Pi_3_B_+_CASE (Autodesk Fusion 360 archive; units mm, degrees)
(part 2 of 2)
delete_face "DeleteFace6"
delete_face "DeleteFace7"
delete_face "DeleteFace8"
delete_face "DeleteFace9"
extrude "Extrude3" cut of existing geometry blind -1.625
offset_faces "OffsetFaces4" distance 0
delete_face "DeleteFace10"
delete_face "DeleteFace11"
extrude "Extrude4" add of existing geometry blind 10.23
move_face "MoveFace8"
move_face "MoveFace9"
hole "Hole3" HoleDepth 10 HoleDiameter 2
hole "Hole4" HoleDepth 10 HoleDiameter 2
hole "Hole5" HoleDepth 10 HoleDiameter 2
hole "Hole6" HoleDepth 10 HoleDiameter 2
offset_faces "OffsetFaces5" distance 1
move_face "MoveFace6"
delete_face "DeleteFace23"
offset_faces "OffsetFaces23" distance 0.4
offset_faces "OffsetFaces24" distance 0.4
delete_face "DeleteFace24"
extrude "Extrude14" cut sketch "Sketch16" along normal blind 8
sketch "Sketch17" plane through (0, 0, 36.4) normal (0, 0, -1) x axis (1, 0, 0)
  line L1 (-29.8898, 23.7088) -> (10.2102, 23.7088)
  line L2 (-29.8898, -16.3912) -> (-29.8898, 23.7088)
  line L3 (10.2102, -16.3912) -> (-29.8898, -16.3912)
  line L4 (10.2102, 23.7088) -> (10.2102, -16.3912)
  curve K1 (5.814, -7.1095) -> (6.1601, -6.5881)
  curve K2 (6.5567, -5.9409) -> (6.8647, -5.3942)
  circle C1 centre (6.1602, -12.3412) radius 1.725
  circle C2 centre (-25.8398, -12.3412) radius 1.725
  circle C3 centre (-25.8398, 19.6588) radius 1.725
  circle C4 centre (6.1602, 19.6588) radius 1.725
  arc A1 centre (-9.8398, 3.6588) radius 19 clockwise from (-27.0735, -4.3412) to (-10.5162, 22.6468)
  arc A2 centre (-9.8398, 3.6588) radius 19 clockwise from (-25.9457, -6.4209) to (-27.0735, -4.3412)
  arc A3 centre (-9.8398, 3.6588) radius 19 clockwise from (4.5049, -8.8003) to (-25.9457, -6.4209)
  arc A4 centre (-9.8398, 3.6588) radius 19 clockwise from (5.814, -7.1095) to (4.5049, -8.8003)
  arc A5 centre (-9.8398, 3.6588) radius 19 clockwise from (6.5567, -5.9409) to (6.1601, -6.5881)
  arc A6 centre (-9.8398, 3.6588) radius 19 clockwise from (8.2681, -2.0948) to (6.8647, -5.3942)
  arc A7 centre (-9.8398, 3.6588) radius 19 clockwise from (-8.1512, 22.5836) to (8.2681, -2.0948)
  arc A8 centre (-9.8398, 3.6588) radius 19 clockwise from (-10.5162, 22.6468) to (-8.1512, 22.5836)
  circle C5 centre (-9.8398, 3.6588) radius 19
hole "Hole3" HoleDepth 10 HoleDiameter 3.3
extrude "Extrude16" cut sketch "Sketch17" profile of A1 A2 A3 A4 K1 A5 K2 A6 A7 A8 C5 against normal blind 2
move_face "MoveFace7"
delete_face "DeleteFace25"
move_face "MoveFace8"
delete_face "DeleteFace26"
chamfer "Chamfer17" distance 0.5
chamfer "Chamfer18" distance 0.3
delete_face "DeleteFace27"
chamfer "Chamfer19" distance 0.3
delete_face "DeleteFace19"
delete_face "DeleteFace20"
delete_face "DeleteFace21"
offset_faces "OffsetFaces10" distance 2
delete_face "DeleteFace22"
chamfer "Chamfer11" distance 3
chamfer "Chamfer12" distance 0.2
fillet "Fillet1" radius 0.5
offset_faces "OffsetFaces11" distance 0.8
offset_faces "OffsetFaces25" distance -0.8
sketch "Sketch18" plane through (0, -24.4, 0) normal (0, 1, 0) x axis (-1, 0, 0)
  line L1 (-18.7605, 30.4) -> (-18.7605, 28.5)
  line L2 (-23.0398, 30.4) -> (-18.7605, 30.4)
  line L3 (-23.0398, 30.3) -> (-23.0398, 30.4)
  line L4 (-43.0097, 30.3) -> (-23.0398, 30.3)
  line L5 (-43.0097, 32.5) -> (-43.0097, 30.3)
  line L6 (-26.9398, 32.5) -> (-43.0097, 32.5)
  line L7 (-26.9398, 35.9) -> (-26.9398, 32.5)
  line L8 (-23.4043, 38.4) -> (-26.9398, 35.9)
  line L9 (-39.9031, 38.4) -> (-23.4043, 38.4)
  line L10 (-52.1398, 26.1633) -> (-39.9031, 38.4)
  line L11 (-52.1398, 25.701) -> (-52.1398, 26.1633)
  line L12 (-51.3898, 25.1706) -> (-52.1398, 25.701)
  line L13 (-51.3898, 16.7) -> (-51.3898, 25.1706)
  line L14 (-47.1398, 16.7) -> (-51.3898, 16.7)
  line L15 (-47.1398, 26.9206) -> (-47.1398, 16.7)
  line L16 (-45.5605, 28.5) -> (-47.1398, 26.9206)
  line L17 (-18.7605, 28.5) -> (-45.5605, 28.5)
  line L18 (-22.4398, 38.4) -> (-24.9398, 35.9)
  line L19 (-24.9398, 35.9) -> (-22.4398, 38.4)
  line L20 (-27.0398, 35.4) -> (-42.9031, 35.4)
  line L21 (-24.9398, 32.5) -> (-24.9398, 35.9)
  line L22 (-24.9398, 35.9) -> (-24.9398, 32.5)
  line L23 (32.8171, 35.4) -> (36.3171, 35.4)
  line L24 (-12.8219, 35.4) -> (32.8171, 35.4)
  line L25 (-16.3219, 35.4) -> (-12.8219, 35.4)
  line L26 (-22.9984, 35.4) -> (-16.3219, 35.4)
  line L27 (-25.0398, 35.4) -> (-22.9984, 35.4)
  line L28 (-27.0398, 35.4) -> (-25.0398, 35.4)
  line L29 (-42.9031, 35.4) -> (-27.0398, 35.4)
  line L30 (-35.5602, 35.4) -> (-42.9031, 35.4)
  line L31 (-35.5602, 35.4) -> (-30.1602, 35.4)
  line L32 (24.4398, 35.4) -> (-30.1602, 35.4)
  line L33 (24.4398, 35.4) -> (29.8398, 35.4)
  line L34 (39.5992, 35.4) -> (29.8398, 35.4)
  line L35 (36.4992, 35.4) -> (39.5992, 35.4)
  line L36 (36.3171, 35.4) -> (36.4992, 35.4)
  line L37 (-39.9031, 38.4) -> (-52.1398, 26.1633)
  line L38 (-23.4043, 38.4) -> (-39.9031, 38.4)
  line L39 (-23.4043, 38.4) -> (-22.4398, 38.4)
  line L40 (-26.9398, 35.9) -> (-23.4043, 38.4)
  line L41 (-24.9398, 35.9) -> (-26.9398, 35.9)
  line L42 (-22.4398, 38.4) -> (-24.9398, 35.9)
extrude "Extrude17" add sketch "Sketch18" profile of L7 L8 L9 L10 L18 L19 L20 L21 L22 L27 L28 L29 L30 L31 L32 L37 L38 L39 L40 L41 L42 along normal blind 10
chamfer "Chamfer20" distance 2.5
work_plane "WorkPlane14"
work_plane "WorkPlane15" AlongDistance 0.5
split "Split4"
split "Split5" bodies "TOP (1) (2)"
combine "Combine4"
remove_body "RemoveBody1"
chamfer "Chamfer21" distance 2.5
chamfer "Chamfer22" distance 2
sketch "Sketch20" plane through (0, 0, 38.4) normal (0, 0, 1) x axis (-1, 0, 0)
  line L1 (-37.4536, 16.9) -> (-39.9031, 19.3495)
  line L2 (-22.4398, 16.9) -> (-37.4536, 16.9)
  line L3 (-22.4398, -17.8816) -> (-22.4398, 16.9)
  line L4 (-20.4215, -19.9) -> (-22.4398, -17.8816)
  line L5 (36.9548, -19.9) -> (-20.4215, -19.9)
  line L6 (40.6992, -23.6444) -> (36.9548, -19.9)
  line L7 (40.6992, -34) -> (40.6992, -23.6444)
  line L8 (43.8173, -34) -> (40.6992, -34)
  line L9 (43.8173, 32) -> (43.8173, -34)
  line L10 (34.5978, 32) -> (43.8173, 32)
  line L11 (34.5978, 31) -> (34.5978, 32)
  line L12 (28.9978, 32) -> (28.9978, 31)
  line L13 (-25.0412, 32) -> (28.9978, 32)
  line L14 (-25.0412, 31) -> (-25.0412, 32)
  line L15 (-30.6412, 32) -> (-30.6412, 31)
  line L16 (-39.9031, 32) -> (-30.6412, 32)
  line L17 (-39.9031, 19.3495) -> (-39.9031, 32)
  line L18 (32.9031, 25.5) -> (32.9031, -8.5)
  line L19 (36.9031, -8.5) -> (36.9031, 25.5)
  line L20 (-15.0969, 25.5) -> (-15.0969, -13.5)
  line L21 (-11.0969, -13.5) -> (-11.0969, 25.5)
  line L22 (34.9031, 20.5) -> (34.9031, 25.5)
  line L23 (33.4031, 25.5) -> (33.4031, -8.5)
  line L24 (36.4031, -8.5) -> (36.4031, 25.5)
  line L25 (29.9898, -20.7569) -> (29.9898, 20.9998)
  line L26 (35.0541, -20.7569) -> (29.9898, -20.7569)
  line L27 (36.6398, -22.3427) -> (35.0541, -20.7569)
  line L28 (36.6398, -26.6671) -> (36.6398, -22.3427)
  line L29 (39.7185, -11.482) -> (39.7185, -26.6201)
  line L30 (38.3561, -11.482) -> (39.7185, -11.482)
  line L31 (37.2703, -10.3962) -> (38.3561, -11.482)
  line L32 (37.2703, 11.8322) -> (37.2703, -10.3962)
  line L33 (38.3561, 12.918) -> (37.2703, 11.8322)
  line L34 (39.7185, 12.918) -> (38.3561, 12.918)
  line L35 (39.7185, 29) -> (39.7185, 12.918)
  line L36 (42.125, 29) -> (39.7185, 29)
  line L37 (42.8321, 29.5) -> (42.125, 29)
  line L38 (42.8321, 35) -> (42.8321, 29.5)
  line L39 (-41.3524, 35) -> (42.8321, 35)
  line L40 (-41.3524, 29.5) -> (-41.3524, 35)
  line L41 (-20.0388, 29.5) -> (-41.3524, 29.5)
  line L42 (-20.0388, -26.6201) -> (-20.0388, 29.5)
  line L43 (-16.9602, -22.3427) -> (-16.9602, -26.6671)
  line L44 (-15.3744, -20.7569) -> (-16.9602, -22.3427)
  line L45 (-10.3102, -20.7569) -> (-15.3744, -20.7569)
  line L46 (-10.3102, 20.9998) -> (-10.3102, -20.7569)
  line L47 (25.9898, 24.9998) -> (-6.3102, 24.9998)
  line L48 (-11.323, -13.3412) -> (-11.3102, -13.3412)
  line L49 (-12.7664, -10.8412) -> (-11.323, -13.3412)
  line L50 (-11.323, -8.3412) -> (-12.7664, -10.8412)
  line L51 (-11.3102, -8.3412) -> (-11.323, -8.3412)
  line L52 (-11.3102, -13.3412) -> (-11.3102, -8.3412)
  line L53 (-11.3102, 15.6588) -> (-11.3102, 20.6588)
  line L54 (-11.323, 15.6588) -> (-11.3102, 15.6588)
  line L55 (-12.7664, 18.1588) -> (-11.323, 15.6588)
  line L56 (-11.323, 20.6588) -> (-12.7664, 18.1588)
  line L57 (-11.3102, 20.6588) -> (-11.323, 20.6588)
  line L58 (-11.3102, 9.8588) -> (-11.3102, 14.8588)
  line L59 (-11.323, 9.8588) -> (-11.3102, 9.8588)
  line L60 (-12.7664, 12.3588) -> (-11.323, 9.8588)
  line L61 (-11.323, 14.8588) -> (-12.7664, 12.3588)
  line L62 (-11.3102, 14.8588) -> (-11.323, 14.8588)
  line L63 (-11.3102, 4.0588) -> (-11.3102, 9.0588)
  line L64 (-11.323, 4.0588) -> (-11.3102, 4.0588)
  line L65 (-12.7664, 6.5588) -> (-11.323, 4.0588)
  line L66 (-11.323, 9.0588) -> (-12.7664, 6.5588)
  line L67 (-11.3102, 9.0588) -> (-11.323, 9.0588)
  line L68 (-11.3102, -1.7412) -> (-11.3102, 3.2588)
  line L69 (-11.323, -1.7412) -> (-11.3102, -1.7412)
  line L70 (-12.7664, 0.7588) -> (-11.323, -1.7412)
  line L71 (-11.323, 3.2588) -> (-12.7664, 0.7588)
  line L72 (-11.3102, 3.2588) -> (-11.323, 3.2588)
  line L73 (-15.1602, 1.1588) -> (-13.4592, 1.1588)
  line L74 (-15.1602, 6.1588) -> (-15.1602, 1.1588)
  line L75 (-13.4592, 6.1588) -> (-15.1602, 6.1588)
  line L76 (-12.0158, 3.6588) -> (-13.4592, 6.1588)
  line L77 (-13.4592, 1.1588) -> (-12.0158, 3.6588)
  line L78 (-15.1602, -5.4412) -> (-15.1602, -10.4412)
  line L79 (-13.4592, -5.4412) -> (-15.1602, -5.4412)
  line L80 (-12.0158, -7.9412) -> (-13.4592, -5.4412)
  line L81 (-13.4592, -10.4412) -> (-12.0158, -7.9412)
  line L82 (-15.1602, -10.4412) -> (-13.4592, -10.4412)
  line L83 (-15.1602, 0.3588) -> (-15.1602, -4.6412)
  line L84 (-13.4592, 0.3588) -> (-15.1602, 0.3588)
  line L85 (-12.0158, -2.1412) -> (-13.4592, 0.3588)
  line L86 (-13.4592, -4.6412) -> (-12.0158, -2.1412)
  line L87 (-15.1602, -4.6412) -> (-13.4592, -4.6412)
  line L88 (-13.4592, 11.9588) -> (-15.1602, 11.9588)
  line L89 (-12.0158, 9.4588) -> (-13.4592, 11.9588)
  line L90 (-13.4592, 6.9588) -> (-12.0158, 9.4588)
  line L91 (-15.1602, 6.9588) -> (-13.4592, 6.9588)
  line L92 (-15.1602, 11.9588) -> (-15.1602, 6.9588)
  line L93 (-15.1602, 17.7588) -> (-15.1602, 12.7588)
  line L94 (-13.4592, 17.7588) -> (-15.1602, 17.7588)
  line L95 (-12.0158, 15.2588) -> (-13.4592, 17.7588)
  line L96 (-13.4592, 12.7588) -> (-12.0158, 15.2588)
  line L97 (-15.1602, 12.7588) -> (-13.4592, 12.7588)
  line L98 (-11.3102, -7.5412) -> (-11.3102, -2.5412)
  line L99 (-11.323, -7.5412) -> (-11.3102, -7.5412)
  line L100 (-12.7664, -5.0412) -> (-11.323, -7.5412)
  line L101 (-11.323, -2.5412) -> (-12.7664, -5.0412)
  line L102 (-11.3102, -2.5412) -> (-11.323, -2.5412)
  line L103 (30.9898, -8.3412) -> (30.9898, -13.3412)
  line L104 (31.7473, -8.3412) -> (30.9898, -8.3412)
  line L105 (33.1907, -10.8412) -> (31.7473, -8.3412)
  line L106 (31.7473, -13.3412) -> (33.1907, -10.8412)
  line L107 (30.9898, -13.3412) -> (31.7473, -13.3412)
  line L108 (31.7473, 14.8588) -> (30.9898, 14.8588)
  line L109 (33.1907, 12.3588) -> (31.7473, 14.8588)
  line L110 (31.7473, 9.8588) -> (33.1907, 12.3588)
  line L111 (30.9898, 9.8588) -> (31.7473, 9.8588)
  line L112 (30.9898, 14.8588) -> (30.9898, 9.8588)
  line L113 (31.7473, 9.0588) -> (30.9898, 9.0588)
  line L114 (33.1907, 6.5588) -> (31.7473, 9.0588)
  line L115 (31.7473, 4.0588) -> (33.1907, 6.5588)
  line L116 (30.9898, 4.0588) -> (31.7473, 4.0588)
  line L117 (30.9898, 9.0588) -> (30.9898, 4.0588)
  line L118 (31.7473, 3.2588) -> (30.9898, 3.2588)
  line L119 (33.1907, 0.7588) -> (31.7473, 3.2588)
  line L120 (31.7473, -1.7412) -> (33.1907, 0.7588)
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  point P28 (34.9031, 25.5)
  point P41 (34.9031, 25.5)
  point P42 (34.9031, 20.5)
  point P43 (34.9031, 20.5)
  coincident P28 P41
  vertical L22
  coincident P42 P43
  dimension "d238" distance P41 P42 = 5
extrude "Extrude19" add sketch "Sketch20" against normal blind 8
chamfer "Chamfer24" distance 0.5
offset_faces "OffsetFaces26" distance -3.536
delete_face "DeleteFace28"
chamfer "Chamfer25" distance 3
remove_instance "RemoveInstance1"
offset_faces "OffsetFaces6" distance 1
work_axis "WorkAxis5"
work_plane "WorkPlane16"
work_plane "WorkPlane17" AlongDistance -50
move_face "MoveFace9"
position "Position18"
position "Position19"
move_face "MoveFace10"
sketch "Sketch21" plane through (0, 0, 28.4) normal (0, 0, 1) x axis (-1, 0, 0)
  line L1 (29.9898, -20.7569) -> (29.9898, 20.9998)
  line L2 (35.0541, -20.7569) -> (29.9898, -20.7569)
  line L3 (36.6398, -22.3427) -> (35.0541, -20.7569)
  line L4 (36.6398, -26.6671) -> (36.6398, -22.3427)
  line L5 (39.7185, -11.482) -> (39.7185, -26.6201)
  line L6 (38.3561, -11.482) -> (39.7185, -11.482)
  line L7 (37.2703, -10.3962) -> (38.3561, -11.482)
  line L8 (37.2703, 11.8322) -> (37.2703, -10.3962)
  line L9 (38.3561, 12.918) -> (37.2703, 11.8322)
  line L10 (39.7185, 12.918) -> (38.3561, 12.918)
  line L11 (39.7185, 29) -> (39.7185, 12.918)
  line L12 (42.125, 29) -> (39.7185, 29)
  line L13 (42.8321, 29.5) -> (42.125, 29)
  line L14 (42.8321, 35) -> (42.8321, 29.5)
  line L15 (-41.3524, 35) -> (42.8321, 35)
  line L16 (-41.3524, 29.5) -> (-41.3524, 35)
  line L17 (-20.0388, 29.5) -> (-41.3524, 29.5)
  line L18 (-20.0388, -26.6201) -> (-20.0388, 29.5)
  line L19 (-16.9602, -22.3427) -> (-16.9602, -26.6671)
  line L20 (-15.3744, -20.7569) -> (-16.9602, -22.3427)
  line L21 (-10.3102, -20.7569) -> (-15.3744, -20.7569)
  line L22 (-10.3102, 20.9998) -> (-10.3102, -20.7569)
  line L23 (25.9898, 24.9998) -> (-6.3102, 24.9998)
  line L24 (-11.323, -13.3412) -> (-11.3102, -13.3412)
  line L25 (-12.7664, -10.8412) -> (-11.323, -13.3412)
  line L26 (-11.323, -8.3412) -> (-12.7664, -10.8412)
  line L27 (-11.3102, -8.3412) -> (-11.323, -8.3412)
  line L28 (-11.3102, -13.3412) -> (-11.3102, -8.3412)
  line L29 (-11.3102, 15.6588) -> (-11.3102, 20.6588)
  line L30 (-11.323, 15.6588) -> (-11.3102, 15.6588)
  line L31 (-12.7664, 18.1588) -> (-11.323, 15.6588)
  line L32 (-11.323, 20.6588) -> (-12.7664, 18.1588)
  line L33 (-11.3102, 20.6588) -> (-11.323, 20.6588)
  line L34 (-11.3102, 9.8588) -> (-11.3102, 14.8588)
  line L35 (-11.323, 9.8588) -> (-11.3102, 9.8588)
  line L36 (-12.7664, 12.3588) -> (-11.323, 9.8588)
  line L37 (-11.323, 14.8588) -> (-12.7664, 12.3588)
  line L38 (-11.3102, 14.8588) -> (-11.323, 14.8588)
  line L39 (-11.3102, 4.0588) -> (-11.3102, 9.0588)
  line L40 (-11.323, 4.0588) -> (-11.3102, 4.0588)
  line L41 (-12.7664, 6.5588) -> (-11.323, 4.0588)
  line L42 (-11.323, 9.0588) -> (-12.7664, 6.5588)
  line L43 (-11.3102, 9.0588) -> (-11.323, 9.0588)
  line L44 (-11.3102, -1.7412) -> (-11.3102, 3.2588)
  line L45 (-11.323, -1.7412) -> (-11.3102, -1.7412)
  line L46 (-12.7664, 0.7588) -> (-11.323, -1.7412)
  line L47 (-11.323, 3.2588) -> (-12.7664, 0.7588)
  line L48 (-11.3102, 3.2588) -> (-11.323, 3.2588)
  line L49 (-15.1602, 1.1588) -> (-13.4592, 1.1588)
  line L50 (-15.1602, 6.1588) -> (-15.1602, 1.1588)
  line L51 (-13.4592, 6.1588) -> (-15.1602, 6.1588)
  line L52 (-12.0158, 3.6588) -> (-13.4592, 6.1588)
  line L53 (-13.4592, 1.1588) -> (-12.0158, 3.6588)
  line L54 (-15.1602, -5.4412) -> (-15.1602, -10.4412)
  line L55 (-13.4592, -5.4412) -> (-15.1602, -5.4412)
  line L56 (-12.0158, -7.9412) -> (-13.4592, -5.4412)
  line L57 (-13.4592, -10.4412) -> (-12.0158, -7.9412)
  line L58 (-15.1602, -10.4412) -> (-13.4592, -10.4412)
  line L59 (-15.1602, 0.3588) -> (-15.1602, -4.6412)
  line L60 (-13.4592, 0.3588) -> (-15.1602, 0.3588)
  line L61 (-12.0158, -2.1412) -> (-13.4592, 0.3588)
  line L62 (-13.4592, -4.6412) -> (-12.0158, -2.1412)
  line L63 (-15.1602, -4.6412) -> (-13.4592, -4.6412)
  line L64 (-13.4592, 11.9588) -> (-15.1602, 11.9588)
  line L65 (-12.0158, 9.4588) -> (-13.4592, 11.9588)
  line L66 (-13.4592, 6.9588) -> (-12.0158, 9.4588)
  line L67 (-15.1602, 6.9588) -> (-13.4592, 6.9588)
  line L68 (-15.1602, 11.9588) -> (-15.1602, 6.9588)
  line L69 (-15.1602, 17.7588) -> (-15.1602, 12.7588)
  line L70 (-13.4592, 17.7588) -> (-15.1602, 17.7588)
  line L71 (-12.0158, 15.2588) -> (-13.4592, 17.7588)
  line L72 (-13.4592, 12.7588) -> (-12.0158, 15.2588)
  line L73 (-15.1602, 12.7588) -> (-13.4592, 12.7588)
  line L74 (-11.3102, -7.5412) -> (-11.3102, -2.5412)
  line L75 (-11.323, -7.5412) -> (-11.3102, -7.5412)
  line L76 (-12.7664, -5.0412) -> (-11.323, -7.5412)
  line L77 (-11.323, -2.5412) -> (-12.7664, -5.0412)
  line L78 (-11.3102, -2.5412) -> (-11.323, -2.5412)
  line L79 (30.9898, -8.3412) -> (30.9898, -13.3412)
  line L80 (31.7473, -8.3412) -> (30.9898, -8.3412)
  line L81 (33.1907, -10.8412) -> (31.7473, -8.3412)
  line L82 (31.7473, -13.3412) -> (33.1907, -10.8412)
  line L83 (30.9898, -13.3412) -> (31.7473, -13.3412)
  line L84 (31.7473, 14.8588) -> (30.9898, 14.8588)
  line L85 (33.1907, 12.3588) -> (31.7473, 14.8588)
  line L86 (31.7473, 9.8588) -> (33.1907, 12.3588)
  line L87 (30.9898, 9.8588) -> (31.7473, 9.8588)
  line L88 (30.9898, 14.8588) -> (30.9898, 9.8588)
  line L89 (31.7473, 9.0588) -> (30.9898, 9.0588)
  line L90 (33.1907, 6.5588) -> (31.7473, 9.0588)
  line L91 (31.7473, 4.0588) -> (33.1907, 6.5588)
  line L92 (30.9898, 4.0588) -> (31.7473, 4.0588)
  line L93 (30.9898, 9.0588) -> (30.9898, 4.0588)
  line L94 (31.7473, 3.2588) -> (30.9898, 3.2588)
  line L95 (33.1907, 0.7588) -> (31.7473, 3.2588)
  line L96 (31.7473, -1.7412) -> (33.1907, 0.7588)
  line L97 (30.9898, -1.7412) -> (31.7473, -1.7412)
  line L98 (30.9898, 3.2588) -> (30.9898, -1.7412)
  line L99 (31.7473, -2.5412) -> (30.9898, -2.5412)
  line L100 (33.1907, -5.0412) -> (31.7473, -2.5412)
  line L101 (31.7473, -7.5412) -> (33.1907, -5.0412)
  line L102 (30.9898, -7.5412) -> (31.7473, -7.5412)
  line L103 (30.9898, -2.5412) -> (30.9898, -7.5412)
  line L104 (30.9898, 20.6588) -> (30.9898, 15.6588)
  line L105 (31.7473, 20.6588) -> (30.9898, 20.6588)
  line L106 (33.1907, 18.1588) -> (31.7473, 20.6588)
  line L107 (31.7473, 15.6588) -> (33.1907, 18.1588)
  line L108 (30.9898, 15.6588) -> (31.7473, 15.6588)
  line L109 (34.8398, 6.1588) -> (33.8835, 6.1588)
  line L110 (34.8398, 1.1588) -> (34.8398, 6.1588)
  line L111 (33.8835, 1.1588) -> (34.8398, 1.1588)
  line L112 (32.4402, 3.6588) -> (33.8835, 1.1588)
  line L113 (33.8835, 6.1588) -> (32.4402, 3.6588)
  line L114 (34.8398, -4.6412) -> (34.8398, 0.3588)
  line L115 (33.8835, -4.6412) -> (34.8398, -4.6412)
  line L116 (32.4402, -2.1412) -> (33.8835, -4.6412)
  line L117 (33.8835, 0.3588) -> (32.4402, -2.1412)
  line L118 (34.8398, 0.3588) -> (33.8835, 0.3588)
  line L119 (34.8398, 11.9588) -> (33.8835, 11.9588)
  line L120 (34.8398, 6.9588) -> (34.8398, 11.9588)
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hole "Hole1" HoleDepth 6.4 HoleDiameter 2
component_insert "Component Insert"
step "00000000-0000-0000-0000-000000000000"
base_feature "Base Feature1"
position "Position20"
step "00000000-0000-0000-0000-000000000000"
offset_faces "OffsetFaces1" distance 5
work_plane "WorkPlane18" AlongDistance 0
sketch "Sketch22" plane through (-1.9571, -1.5003, 38.4) normal (0, 0, 1) x axis (1, 0, 0)
  line L1 (-43.1827, -12.5382) -> (-43.1827, 15.0673)
  line L2 (-37.946, 10.0003) -> (-32.946, 10.0003)
  line L3 (-46.446, 11.5003) -> (-39.446, 11.5003)
  line L4 (-39.446, 8.5003) -> (-46.446, 8.5003)
  line L5 (-47.946, 10.0003) -> (-37.946, 10.0003)
  arc A1 centre (-32.946, 10.0003) radius 1.5 clockwise from (-34.446, 10.0003) to (-31.446, 10.0003)
  arc A2 centre (-46.446, 10.0003) radius 1.5 clockwise from (-46.446, 8.5003) to (-46.446, 11.5003)
  arc A3 centre (-39.446, 10.0003) radius 1.5 clockwise from (-39.446, 11.5003) to (-39.446, 8.5003)
  point P4 (-32.946, 10.0003)
  point P7 (-32.946, 10.0003)
  point P8 (-37.946, 10.0003)
  point P15 (-47.946, 10.0003)
  coincident P4 P7
  perpendicular L1 L2
  tangent L3 A2
  tangent A2 L4
  parallel L3 L4
  tangent L4 A3
  tangent L3 A3
  midpoint P8 A3
  midpoint A2 P15
  perpendicular L1 L5
  dimension "d259" distance P7 P8 = 5
  dimension "d260" diameter A2 = 3
emboss "Emboss1" sketch "Sketch22" Depth -10.895 Horizontal Distance -4.25 Vertical Distance 2
rectangular_pattern "R-Pattern2" uSpaceDistance -35 vSpaceDistance 0
chamfer "Chamfer26" distance 0.3
sketch "Sketch23" plane through (0, 0, 35.4) normal (0, 0, 1) x axis (-1, 0, 0)
  line L1 (36.3171, -25.269) -> (36.3171, -21)
  line L2 (-12.8219, -28.769) -> (32.8171, -28.769)
  line L3 (-16.3219, -21) -> (-16.3219, -25.269)
  line L4 (-22.9984, -21) -> (-16.3219, -21)
  line L5 (-25.0398, -18.9586) -> (-22.9984, -21)
  line L6 (-25.0398, 22.3) -> (-25.0398, -18.9586)
  line L7 (-27.0398, 24.3) -> (-25.0398, 22.3)
  line L8 (-42.9031, 24.3) -> (-27.0398, 24.3)
  line L9 (-42.9031, -32) -> (-42.9031, 24.3)
  line L10 (-35.5602, -32) -> (-42.9031, -32)
  line L11 (24.4398, -32) -> (-30.1602, -32)
  line L12 (39.5992, -32) -> (29.8398, -32)
  line L13 (39.5992, -24.1) -> (39.5992, -32)
  line L14 (36.4992, -21) -> (39.5992, -24.1)
  line L15 (36.3171, -21) -> (36.4992, -21)
  line L16 (-27.0398, 11.4) -> (-25.0398, 11.4)
  line L17 (-24.9398, 14.4) -> (-39.9031, 14.4)
  line L18 (-23.0398, 11.4) -> (-27.0398, 11.4)
  line L19 (-27.0398, 11.4) -> (-25.0398, 11.4)
  line L20 (-39.7678, 0.7934) -> (-29.1612, 11.4)
  line L21 (-27.0398, 9.2787) -> (-37.6464, -1.3279)
  line L22 (-39.7678, -1.3279) -> (-27.0398, 11.4)
  line L23 (-12.0398, 11.4) -> (-27.0398, 11.4)
  line L24 (-37.6464, 11.4) -> (-27.0398, 0.7934)
  line L25 (-29.1612, -1.3279) -> (-39.7678, 9.2787)
  line L26 (-33.5398, 12.9) -> (-28.5398, 12.9)
  line L27 (-28.5398, 9.9) -> (-33.5398, 9.9)
  line L28 (-35.0398, 11.4) -> (-27.0398, 11.4)
  arc A1 centre (32.8171, -25.269) radius 3.5 clockwise from (36.3171, -25.269) to (32.8171, -28.769)
  arc A2 centre (-12.8219, -25.269) radius 3.5 clockwise from (-12.8219, -28.769) to (-16.3219, -25.269)
  arc A3 centre (-32.8602, -32) radius 2.7 clockwise from (-35.5602, -32) to (-30.1602, -32)
  arc A4 centre (27.1398, -32) radius 2.7 clockwise from (24.4398, -32) to (29.8398, -32)
  arc A5 centre (-38.7071, -0.2673) radius 1.5 clockwise from (-37.6464, -1.3279) to (-39.7678, 0.7934)
  arc A6 centre (-28.1005, 10.3393) radius 1.5 clockwise from (-29.1612, 11.4) to (-27.0398, 9.2787)
  arc A7 centre (-38.7071, 10.3393) radius 1.5 clockwise from (-39.7678, 9.2787) to (-37.6464, 11.4)
  arc A8 centre (-28.1005, -0.2673) radius 1.5 clockwise from (-27.0398, 0.7934) to (-29.1612, -1.3279)
  arc A9 centre (-33.5398, 11.4) radius 1.5 clockwise from (-33.5398, 9.9) to (-33.5398, 12.9)
  arc A10 centre (-28.5398, 11.4) radius 1.5 clockwise from (-28.5398, 12.9) to (-28.5398, 9.9)
  point P25 (-25.0398, 11.4)
  point P26 (-27.0398, 11.4)
  point P37 (-39.7678, -1.3279)
  point P39 (-33.4038, 5.036)
  point P52 (-35.0398, 11.4)
  point P30 (-27.0398, 11.4)
  coincident L6 P25
  perpendicular L6 L16
  parallel L16 L18
  perpendicular L6 L19
  tangent L20 A5
  tangent A5 L21
  parallel L20 L21
  tangent L21 A6
  tangent L20 A6
  midpoint P26 A6
  midpoint A5 P37
  midpoint L22 P39
  tangent L24 A7
  tangent A7 L25
  parallel L24 L25
  tangent L25 A8
  tangent L24 A8
  tangent L26 A9
  tangent A9 L27
  parallel L26 L27
  tangent L27 A10
  tangent L26 A10
  midpoint P26 A10
  midpoint A9 P52
  parallel L18 L28
  dimension "d271" distance L16 L17 = 3
  dimension "d283" distance P25 P30 = 2
  dimension "d284" distance P26 P37 = 18
  dimension "d285" angle L22 L23 = 135 (= "Angular Dimension-2")
  dimension "d286" diameter A5 = 3
  dimension "d295" diameter A7 = 3
  dimension "d296" diameter A9 = 3
extrude "Extrude7" cut sketch "Sketch23" profile of L20 A6 L26 A9 L27 A10 against normal blind 5
chamfer "Chamfer14" distance 0.3
rectangular_pattern "R-Pattern3" uSpaceDistance 35 vSpaceDistance 0
chamfer "Chamfer15" distance 0.3
delete_face "DeleteFace23"
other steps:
base_feature "Base Feature1" bodies "PI3 A/B_MOUNT  (1) (2)"
move_face "MoveFace3"
offset_faces "OffsetFaces2" distance -0.4
chamfer "Chamfer2" distance 0.75
hole "Hole7" HoleDepth 6.4 HoleDiameter 2
create_component "CreateComponent1"
create_component "CreateComponent1"
create_component "CreateComponent2"
create_component "CreateComponent2"
create_component "CreateComponent3"
create_component "CreateComponent4"
create_component "CreateComponent5"
create_component "CreateComponent6"
create_component "CreateComponent7"
create_component "CreateComponent8"
create_component "CreateComponent9"
create_component "CreateComponent10"
create_component "CreateComponent1"
remove_body "RemoveBody1"
create_component "CreateComponent11"
create_component "CreateComponent12"
remove_body "RemoveBody1"
hole "Hole1" HoleDepth 3 HoleDiameter 2.8
create_component "CreateComponent13"
create_component "CreateComponent14"
named bodies: "TOP", "BOTTOM", "base", "PI3 A/B_MOUNT  (1) (2)", "PI_ZERO_MOUNT_1", "TOP (1)", "BOTTOM (1)", "TOP (1) (1)", "TOP (1) (2)"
